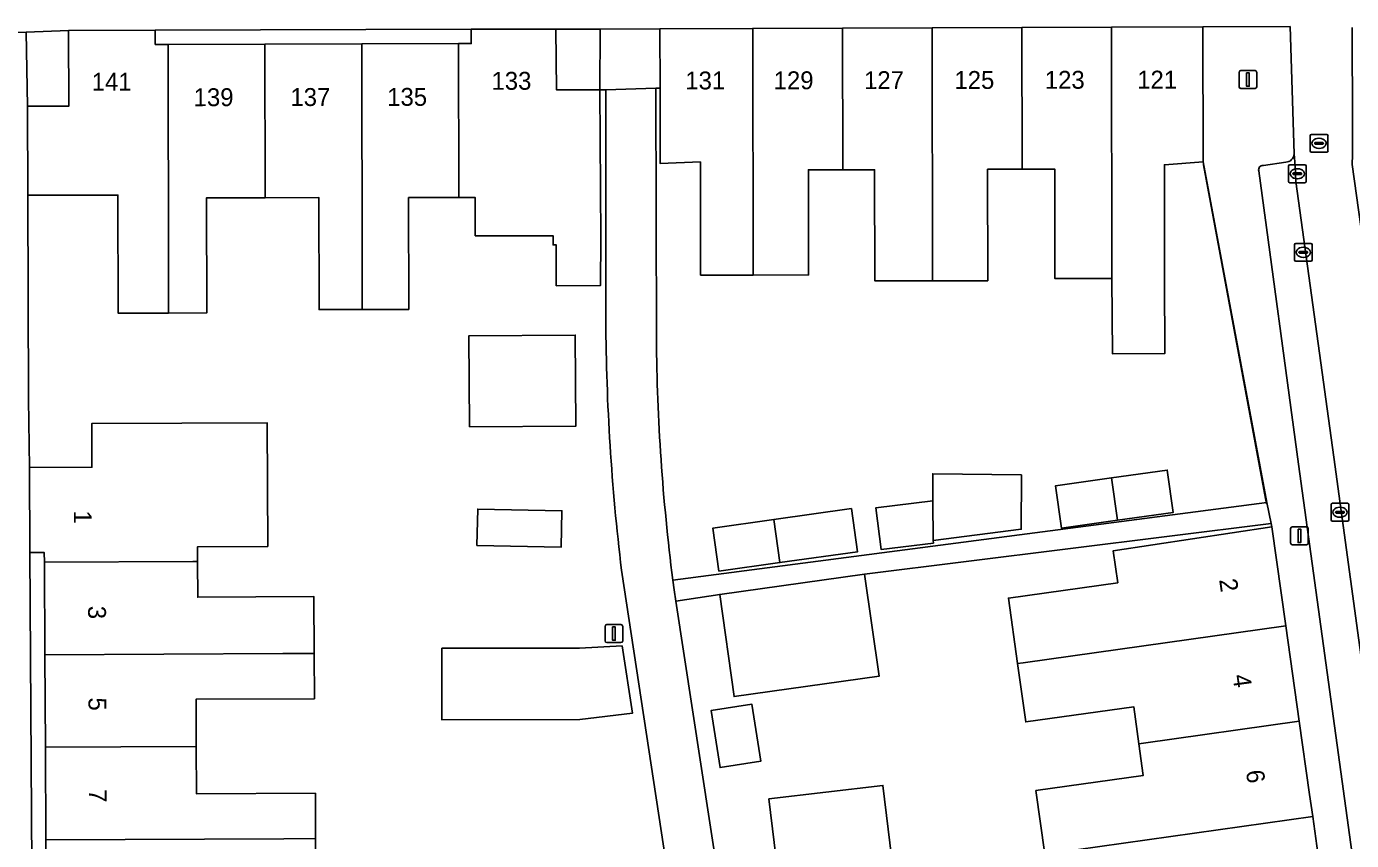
# Model space of a CAD drawing. Extents: x 159716 to 160783, y 383290 to 384031.
# Drawn here: x 160153 to 160227, y 383701.3 to 383746.8 of the extents above; entities that cross this region are included whole.
import ezdxf

# ---------------------------------------------------------------- set-up
doc = ezdxf.new("R2010")
doc.units = 0
for name, color, linetype in [('IMGEO_Erf', 7, 'Continuous'), ('IMGEO_Kolk', 7, 'Continuous'), ('IMGEO_Lichtmast', 7, 'Continuous'), ('IMGEO_Muur', 7, 'Continuous'), ('IMGEO_Pand', 7, 'Continuous'), ('IMGEO_Pand_nummerreeks', 7, 'Continuous'), ('IMGEO_Parkeervlak_open', 7, 'Continuous'), ('IMGEO_Rijbaan_lokaal_open', 7, 'Continuous'), ('IMGEO_Rioolput', 7, 'Continuous'), ('IMGEO_Voetpad_open', 7, 'Continuous')]:
    doc.layers.add(name, color=color, linetype=linetype)

msp = doc.modelspace()

# ---------------------------------------------------------------- linework, layer by layer
at = {"layer": 'IMGEO_Erf'}
for points in [[(160155.314, 383746.591), (160152.949, 383746.498), (160153.028, 383742.368), (160155.333, 383742.372)], [(160177.832, 383746.661), (160160.16, 383746.616), (160160.161, 383745.816), (160160.884, 383745.818), (160166.294, 383745.832), (160171.705, 383745.846), (160177.116, 383745.859), (160177.833, 383745.861)], [(160185.037, 383746.676), (160182.565, 383746.665), (160182.6, 383743.274), (160185.012, 383743.274)], [(160177.737, 383724.449), (160177.702, 383729.531), (160183.646, 383729.572), (160183.681, 383724.49)], [(160208.599, 383721.765), (160208.583, 383718.721), (160203.663, 383718.101), (160203.664, 383717.952), (160200.74, 383717.594), (160200.455, 383719.927), (160203.644, 383720.317), (160203.632, 383721.823)], [(160216.742, 383722.032), (160217.075, 383719.659), (160213.951, 383719.221), (160210.828, 383718.783), (160210.495, 383721.156), (160213.619, 383721.594)], [(160178.15, 383717.82), (160178.189, 383719.85), (160182.898, 383719.759), (160182.858, 383717.729)], [(160199.085, 383719.881), (160199.424, 383717.469), (160195.082, 383716.858), (160191.676, 383716.38), (160191.337, 383718.792), (160194.743, 383719.271)], [(160154.05, 383701.364), (160154.02, 383706.538), (160153.99, 383711.711), (160153.961, 383716.884), (160153.957, 383717.419), (160153.157, 383717.414), (160153.348, 383685.282), (160154.143, 383685.283), (160154.111, 383690.738), (160154.08, 383696.191)], [(160176.185, 383712.069), (160183.885, 383712.083), (160186.26, 383712.204), (160186.848, 383708.451), (160183.892, 383708.086), (160176.193, 383708.071)], [(160194.015, 383705.761), (160191.743, 383705.403), (160191.24, 383708.593), (160193.512, 383708.951)], [(160201.428, 383699.526), (160195.055, 383698.769), (160194.475, 383703.653), (160200.848, 383704.41)]]:
    msp.add_lwpolyline(points, close=True, dxfattribs=at)
for points in [[(160185.356, 383730.393), (160185.356, 383743.275), (160185.012, 383743.274), (160185.077, 383735), (160185.058, 383732.35), (160182.585, 383732.334), (160182.581, 383734.61), (160182.404, 383734.61), (160182.403, 383735.127), (160178.05, 383735.121), (160178.047, 383737.262), (160177.13, 383737.261), (160174.325, 383737.256), (160174.335, 383731.005), (160171.73, 383731.001), (160169.32, 383730.997), (160169.309, 383737.254), (160166.308, 383737.249), (160163.034, 383737.244), (160163.045, 383730.81), (160160.91, 383730.806), (160158.087, 383730.801), (160158.076, 383737.4), (160153.046, 383737.391), (160153.072, 383725.982), (160153.128, 383722.176), (160156.62, 383722.189), (160156.608, 383724.628), (160161.656, 383724.654), (160166.427, 383724.668), (160166.449, 383717.763), (160162.526, 383717.745), (160162.53, 383716.925), (160162.539, 383714.927), (160169.032, 383714.959), (160169.048, 383711.784), (160169.06, 383709.255), (160162.445, 383709.222), (160162.458, 383706.579), (160162.47, 383703.937), (160169.116, 383703.97), (160169.128, 383701.437), (160169.142, 383698.596)], [(160218.753, 383739.261), (160216.582, 383739.087), (160216.595, 383732.738), (160216.604, 383728.537), (160213.674, 383728.531), (160213.648, 383732.733), (160211.596, 383732.729), (160210.464, 383732.727), (160210.454, 383738.849), (160208.624, 383738.846), (160206.693, 383738.842), (160206.703, 383732.609), (160203.623, 383732.604), (160200.393, 383732.598), (160200.382, 383738.814), (160198.599, 383738.811), (160196.677, 383738.808), (160196.686, 383732.934), (160193.598, 383732.928), (160190.654, 383732.923), (160190.642, 383739.252), (160188.394, 383739.16), (160188.384, 383743.366), (160188.154, 383743.37), (160188.179, 383729.368)], [(160189.1, 383715.883), (160222.31, 383720.208), (160218.753, 383739.261)], [(160209.901, 383700.567), (160209.403, 383704.123), (160215.404, 383704.963), (160215.156, 383706.734), (160214.867, 383708.799), (160208.827, 383707.953), (160208.371, 383711.215), (160207.858, 383714.877), (160213.973, 383715.734), (160213.724, 383717.518), (160222.589, 383718.862), (160222.551, 383719.046), (160199.824, 383716.221), (160200.628, 383710.506), (160192.525, 383709.367), (160191.722, 383715.082), (160189.268, 383714.705), (160195.404, 383674.755)], [(160192.049, 383678.265), (160186.233, 383716.436)]]:
    msp.add_lwpolyline(points, dxfattribs=at)
for centre, radius, start, end in [((160305.947, 383730.964), 120.593, 180.27148, 186.91952), ((160302.297, 383730.388), 114.122, 180.51214, 187.30211)]:
    msp.add_arc(centre, radius, start, end, dxfattribs=at)
at = {"layer": 'IMGEO_Kolk'}
for p, q in [((160223.848, 383733.771), (160223.848, 383734.623)), ((160223.923, 383734.697), (160224.775, 383734.697)), ((160224.336, 383734.477), (160224.361, 383734.477)), ((160224.849, 383734.623), (160224.849, 383733.771)), ((160224.775, 383733.697), (160223.923, 383733.697)), ((160224.107, 383734.191), (160224.107, 383734.203)), ((160224.545, 383734.154), (160224.147, 383734.154)), ((160224.15, 383734.24), (160224.548, 383734.24)), ((160224.359, 383733.917), (160224.334, 383733.917)), ((160224.591, 383734.203), (160224.591, 383734.191)), ((160225.898, 383719.245), (160225.898, 383720.097)), ((160225.973, 383720.171), (160226.825, 383720.171)), ((160226.157, 383719.665), (160226.157, 383719.677)), ((160226.595, 383719.628), (160226.197, 383719.628)), ((160226.2, 383719.714), (160226.598, 383719.714)), ((160226.386, 383719.951), (160226.411, 383719.951)), ((160226.641, 383719.677), (160226.641, 383719.665)), ((160226.899, 383720.097), (160226.899, 383719.245)), ((160226.825, 383719.171), (160225.973, 383719.171)), ((160226.409, 383719.391), (160226.384, 383719.391))]:
    msp.add_line(p, q, dxfattribs=at)
for points in [[(160223.848, 383733.771), (160223.848, 383734.623)], [(160223.923, 383734.697), (160224.775, 383734.697)], [(160224.849, 383734.623), (160224.849, 383733.771)], [(160224.775, 383733.697), (160223.923, 383733.697)], [(160225.898, 383719.245), (160225.898, 383720.097)], [(160225.973, 383720.171), (160226.825, 383720.171)], [(160226.899, 383720.097), (160226.899, 383719.245)], [(160226.825, 383719.171), (160225.973, 383719.171)]]:
    msp.add_lwpolyline(points, dxfattribs=at)
for centre, radius, start, end in [((160223.925, 383734.621), 0.0765, 91.55205, 178.44795), ((160223.925, 383734.621), 0.0765, 91.55205, 178.44795), ((160224.773, 383734.621), 0.0765, 1.55205, 88.44795), ((160224.773, 383734.621), 0.0765, 1.55205, 88.44795), ((160223.925, 383733.773), 0.0765, 181.55205, 268.44795), ((160223.925, 383733.773), 0.0765, 181.55205, 268.44795), ((160224.147, 383734.2), 0.0403, 85.87752, 175.75265), ((160224.144, 383734.19), 0.0366, 178.93798, 274.71019), ((160224.548, 383734.197), 0.043, 264.86636, 352.45326), ((160224.552, 383734.202), 0.0386, 1.73085, 96.63898), ((160224.773, 383733.773), 0.0765, 271.55205, 358.44795), ((160224.773, 383733.773), 0.0765, 271.55205, 358.44795), ((160225.975, 383720.095), 0.0765, 91.55205, 178.44795), ((160225.975, 383720.095), 0.0765, 91.55205, 178.44795), ((160226.197, 383719.674), 0.0403, 85.87752, 175.75265), ((160226.194, 383719.664), 0.0366, 178.93798, 274.71019), ((160226.598, 383719.671), 0.043, 264.86636, 352.45326), ((160226.602, 383719.676), 0.0386, 1.73085, 96.63898), ((160226.823, 383720.095), 0.0765, 1.55205, 88.44795), ((160226.823, 383720.095), 0.0765, 1.55205, 88.44795), ((160225.975, 383719.247), 0.0765, 181.55205, 268.44795), ((160225.975, 383719.247), 0.0765, 181.55205, 268.44795), ((160226.823, 383719.247), 0.0765, 271.55205, 358.44795), ((160226.823, 383719.247), 0.0765, 271.55205, 358.44795)]:
    msp.add_arc(centre, radius, start, end, dxfattribs=at)
for centre, major_axis, ratio, start_param, end_param in [((160224.335, 383734.197), (-0.387, 0.002), 0.722429, 4.712389, 7.853982), ((160224.36, 383734.197), (-0.39, 0.002), 0.717154, 1.570796, 4.712389), ((160226.385, 383719.671), (-0.387, 0.002), 0.722429, 4.712389, 7.853982), ((160226.41, 383719.671), (-0.39, 0.002), 0.717154, 1.570796, 4.712389)]:
    msp.add_ellipse(centre, major_axis=major_axis, ratio=ratio, start_param=start_param, end_param=end_param, dxfattribs=at)
at = {"layer": 'IMGEO_Lichtmast'}
for p, q in [((160220.758, 383743.451), (160220.758, 383744.251)), ((160220.758, 383744.251), (160220.758, 383743.451)), ((160220.858, 383744.351), (160221.648, 383744.351)), ((160221.648, 383744.351), (160220.858, 383744.351)), ((160221.748, 383744.251), (160221.748, 383743.451)), ((160221.748, 383743.451), (160221.748, 383744.251)), ((160221.648, 383743.351), (160220.858, 383743.351)), ((160220.858, 383743.351), (160221.648, 383743.351)), ((160223.634, 383717.956), (160223.634, 383718.756)), ((160223.634, 383718.756), (160223.634, 383717.956)), ((160223.734, 383718.856), (160224.524, 383718.856)), ((160224.524, 383718.856), (160223.734, 383718.856)), ((160224.624, 383718.756), (160224.624, 383717.956)), ((160224.624, 383717.956), (160224.624, 383718.756)), ((160224.524, 383717.856), (160223.734, 383717.856)), ((160223.734, 383717.856), (160224.524, 383717.856)), ((160185.308, 383712.492), (160185.308, 383713.292)), ((160185.308, 383713.292), (160185.308, 383712.492)), ((160185.408, 383713.392), (160186.198, 383713.392)), ((160186.198, 383713.392), (160185.408, 383713.392)), ((160186.298, 383713.292), (160186.298, 383712.492)), ((160186.298, 383712.492), (160186.298, 383713.292)), ((160186.198, 383712.392), (160185.408, 383712.392)), ((160185.408, 383712.392), (160186.198, 383712.392))]:
    msp.add_line(p, q, dxfattribs=at)
for points in [[(160221.178, 383744.226), (160221.328, 383744.226), (160221.328, 383743.476), (160221.178, 383743.476), (160221.178, 383744.226)], [(160224.054, 383718.731), (160224.204, 383718.731), (160224.204, 383717.981), (160224.054, 383717.981), (160224.054, 383718.731)], [(160185.728, 383713.267), (160185.878, 383713.267), (160185.878, 383712.517), (160185.728, 383712.517), (160185.728, 383713.267)]]:
    msp.add_lwpolyline(points, dxfattribs=at)
for centre, start, end in [((160220.858, 383744.251), 90, 180), ((160220.858, 383744.251), 90, 180), ((160221.648, 383744.251), 0, 90), ((160221.648, 383744.251), 360, 90), ((160220.858, 383743.451), 180, 270), ((160220.858, 383743.451), 180, 270), ((160221.648, 383743.451), 270, 0), ((160221.648, 383743.451), 270, 0), ((160223.734, 383718.756), 90, 180), ((160223.734, 383718.756), 90, 180), ((160224.524, 383718.756), 0, 90), ((160224.524, 383718.756), 360, 90), ((160223.734, 383717.956), 180, 270), ((160223.734, 383717.956), 180, 270), ((160224.524, 383717.956), 270, 0), ((160224.524, 383717.956), 270, 0), ((160185.408, 383713.292), 90, 180), ((160185.408, 383713.292), 90, 180), ((160186.198, 383713.292), 0, 90), ((160186.198, 383713.292), 360, 90), ((160185.408, 383712.492), 180, 270), ((160185.408, 383712.492), 180, 270), ((160186.198, 383712.492), 270, 0), ((160186.198, 383712.492), 270, 0)]:
    msp.add_arc(centre, 0.1, start, end, dxfattribs=at)
at = {"layer": 'IMGEO_Muur'}
for points in [[(160218.771, 383739.091), (160222.296, 383720.136)], [(160153.046, 383737.391), (160153.072, 383725.982)]]:
    msp.add_lwpolyline(points, dxfattribs=at)
at = {"layer": 'IMGEO_Pand'}
for points in [[(160160.884, 383745.818), (160160.161, 383745.816), (160160.16, 383746.616), (160155.314, 383746.591), (160155.333, 383742.372), (160153.028, 383742.368), (160153.046, 383737.391), (160158.076, 383737.4), (160158.087, 383730.801), (160160.91, 383730.806), (160160.906, 383732.899)], [(160185.012, 383743.274), (160182.6, 383743.274), (160182.565, 383746.665), (160177.832, 383746.661), (160177.833, 383745.861), (160177.116, 383745.859), (160177.13, 383737.439), (160177.13, 383737.261), (160178.047, 383737.262), (160178.05, 383735.121), (160182.403, 383735.127), (160182.404, 383734.61), (160182.581, 383734.61), (160182.585, 383732.334), (160185.058, 383732.35), (160185.077, 383735)], [(160193.572, 383746.707), (160188.376, 383746.69), (160188.384, 383743.366), (160188.394, 383739.16), (160190.642, 383739.252), (160190.654, 383732.923), (160193.598, 383732.928)], [(160198.585, 383746.723), (160193.572, 383746.707), (160193.598, 383732.928), (160196.686, 383732.934), (160196.677, 383738.808), (160198.599, 383738.811)], [(160203.598, 383746.74), (160198.585, 383746.723), (160198.599, 383738.811), (160200.382, 383738.814), (160200.393, 383732.598), (160203.623, 383732.604), (160203.623, 383732.705)], [(160208.61, 383746.756), (160203.598, 383746.74), (160203.623, 383732.705), (160203.623, 383732.604), (160206.703, 383732.609), (160206.693, 383738.842), (160208.624, 383738.846), (160208.624, 383739.025)], [(160213.623, 383746.772), (160208.61, 383746.756), (160208.624, 383739.025), (160208.624, 383738.846), (160210.454, 383738.849), (160210.464, 383732.727), (160211.596, 383732.729), (160213.648, 383732.733)], [(160216.582, 383739.087), (160218.753, 383739.261), (160218.726, 383746.789), (160213.623, 383746.772), (160213.648, 383732.733), (160213.674, 383728.531), (160216.604, 383728.537), (160216.595, 383732.738)], [(160166.294, 383745.832), (160160.884, 383745.818), (160160.906, 383732.899), (160160.91, 383730.806), (160163.045, 383730.81), (160163.034, 383737.244), (160166.308, 383737.249), (160166.308, 383737.41)], [(160171.705, 383745.846), (160166.294, 383745.832), (160166.308, 383737.41), (160166.308, 383737.249), (160169.309, 383737.254), (160169.32, 383730.997), (160171.73, 383731.001), (160171.727, 383732.905)], [(160177.116, 383745.859), (160171.705, 383745.846), (160171.727, 383732.905), (160171.73, 383731.001), (160174.335, 383731.005), (160174.325, 383737.256), (160177.13, 383737.261), (160177.13, 383737.439)], [(160177.737, 383724.449), (160183.681, 383724.49), (160183.646, 383729.572), (160177.702, 383729.531)], [(160166.427, 383724.668), (160161.656, 383724.654), (160156.608, 383724.628), (160156.62, 383722.189), (160153.128, 383722.176), (160153.157, 383717.414), (160153.957, 383717.419), (160153.961, 383716.884), (160162.263, 383716.923), (160162.53, 383716.925), (160162.526, 383717.745), (160166.449, 383717.763)], [(160208.599, 383721.765), (160203.632, 383721.823), (160203.644, 383720.317), (160203.663, 383718.101), (160208.583, 383718.721)], [(160213.951, 383719.221), (160217.075, 383719.659), (160216.742, 383722.032), (160213.619, 383721.594)], [(160213.619, 383721.594), (160210.495, 383721.156), (160210.828, 383718.783), (160213.951, 383719.221)], [(160203.644, 383720.317), (160200.455, 383719.927), (160200.74, 383717.594), (160203.664, 383717.952), (160203.663, 383718.101)], [(160178.15, 383717.82), (160182.858, 383717.729), (160182.898, 383719.759), (160178.189, 383719.85)], [(160194.743, 383719.271), (160195.082, 383716.858), (160199.424, 383717.469), (160199.085, 383719.881)], [(160194.743, 383719.271), (160191.337, 383718.792), (160191.676, 383716.38), (160195.082, 383716.858)], [(160222.589, 383718.862), (160213.724, 383717.518), (160213.973, 383715.734), (160207.858, 383714.877), (160208.371, 383711.215), (160208.679, 383711.258), (160223.372, 383713.317)], [(160169.032, 383714.959), (160162.539, 383714.927), (160162.53, 383716.925), (160162.263, 383716.923), (160153.961, 383716.884), (160153.99, 383711.711), (160167.301, 383711.776), (160169.048, 383711.784)], [(160200.628, 383710.506), (160199.824, 383716.221), (160191.722, 383715.082), (160192.525, 383709.367)], [(160223.372, 383713.317), (160208.679, 383711.258), (160208.371, 383711.215), (160208.827, 383707.953), (160214.867, 383708.799), (160215.156, 383706.734), (160215.421, 383706.771), (160224.124, 383707.991)], [(160183.892, 383708.086), (160186.848, 383708.451), (160186.26, 383712.204), (160183.885, 383712.083), (160176.185, 383712.069), (160176.193, 383708.071)], [(160169.048, 383711.784), (160167.301, 383711.776), (160153.99, 383711.711), (160154.02, 383706.538), (160162.458, 383706.579), (160162.445, 383709.222), (160169.06, 383709.255)], [(160193.512, 383708.951), (160191.24, 383708.593), (160191.743, 383705.403), (160194.015, 383705.761)], [(160224.124, 383707.991), (160215.421, 383706.771), (160215.156, 383706.734), (160215.404, 383704.963), (160209.403, 383704.123), (160209.901, 383700.567), (160210.329, 383700.627), (160224.873, 383702.664), (160224.7, 383703.909)], [(160169.116, 383703.97), (160162.47, 383703.937), (160162.458, 383706.579), (160154.02, 383706.538), (160154.05, 383701.364), (160167.349, 383701.429), (160169.128, 383701.437)], [(160201.428, 383699.526), (160200.848, 383704.41), (160194.475, 383703.653), (160195.055, 383698.769)], [(160224.873, 383702.664), (160210.329, 383700.627), (160209.901, 383700.567), (160205.61, 383699.966), (160206.053, 383696.806), (160210.344, 383697.407), (160216.339, 383698.247), (160216.642, 383696.079), (160216.889, 383696.114), (160225.615, 383697.337)], [(160162.575, 383698.564), (160166.117, 383698.581), (160169.142, 383698.596), (160169.128, 383701.437), (160167.349, 383701.429), (160154.05, 383701.364), (160154.08, 383696.191), (160162.312, 383696.232), (160162.586, 383696.233)]]:
    msp.add_lwpolyline(points, close=True, dxfattribs=at)
at = {"layer": 'IMGEO_Parkeervlak_open'}
for points in [[(160228.912, 383701.88), (160226.055, 383722.742), (160223.935, 383738.148), (160223.898, 383739.006), (160223.833, 383739.706)], [(160221.858, 383738.755), (160224.075, 383722.353), (160230.414, 383676.339), (160230.994, 383672.299)], [(160223.364, 383739.235), (160222.114, 383739.053)]]:
    msp.add_lwpolyline(points, dxfattribs=at)
for centre, radius, start, end in [((160223.355, 383739.713), 0.478, 271.09867, 359.14514), ((160222.089, 383738.815), 0.239, 84.06933, 194.60153)]:
    msp.add_arc(centre, radius, start, end, dxfattribs=at)
at = {"layer": 'IMGEO_Rijbaan_lokaal_open'}
for points in [[(160148.407, 383684.961), (160153.348, 383685.282), (160153.157, 383717.414), (160153.128, 383722.176), (160153.072, 383725.982), (160153.046, 383737.391), (160153.028, 383742.368), (160152.949, 383746.498)], [(160223.833, 383739.706), (160223.612, 383746.816), (160218.726, 383746.789), (160218.753, 383739.261), (160222.31, 383720.208), (160222.551, 383719.046), (160222.589, 383718.862), (160223.372, 383713.317), (160224.124, 383707.991), (160224.7, 383703.909), (160224.873, 383702.664), (160225.615, 383697.337)], [(160223.612, 383746.816), (160223.833, 383739.706), (160223.898, 383739.006), (160223.935, 383738.148), (160226.055, 383722.742), (160228.912, 383701.88), (160232.18, 383702.315), (160231.558, 383706.805), (160231.311, 383708.492), (160231.158, 383709.718), (160230.618, 383713.556), (160228.88, 383726.194), (160228.773, 383726.987), (160227.082, 383739.102), (160227.092, 383739.638), (160227.094, 383741.298), (160227.08, 383746.76)], [(160224.075, 383722.353), (160221.858, 383738.755)], [(160222.114, 383739.053), (160223.364, 383739.235)], [(160230.994, 383672.299), (160230.414, 383676.339), (160224.075, 383722.353)]]:
    msp.add_lwpolyline(points, dxfattribs=at)
for centre, radius, start, end in [((160157.337, 383744.599), 8.157, 104.90497, 167.10486), ((160223.355, 383739.713), 0.478, 271.09867, 359.14514), ((160222.089, 383738.815), 0.239, 84.06933, 194.60153)]:
    msp.add_arc(centre, radius, start, end, dxfattribs=at)
at = {"layer": 'IMGEO_Rioolput'}
for p, q in [((160224.728, 383739.862), (160224.728, 383740.714)), ((160224.803, 383740.788), (160225.655, 383740.788)), ((160224.987, 383740.282), (160224.987, 383740.294)), ((160225.425, 383740.245), (160225.027, 383740.245)), ((160225.03, 383740.331), (160225.428, 383740.331)), ((160225.216, 383740.568), (160225.241, 383740.568)), ((160225.471, 383740.294), (160225.471, 383740.282)), ((160225.729, 383740.714), (160225.729, 383739.862)), ((160225.655, 383739.788), (160224.803, 383739.788)), ((160225.239, 383740.008), (160225.214, 383740.008)), ((160223.512, 383738.163), (160223.512, 383739.015)), ((160223.587, 383739.089), (160224.439, 383739.089)), ((160224, 383738.869), (160224.025, 383738.869)), ((160224.513, 383739.015), (160224.513, 383738.163)), ((160224.439, 383738.089), (160223.587, 383738.089)), ((160223.771, 383738.583), (160223.771, 383738.595)), ((160224.209, 383738.546), (160223.811, 383738.546)), ((160223.814, 383738.632), (160224.212, 383738.632)), ((160224.023, 383738.309), (160223.998, 383738.309)), ((160224.255, 383738.595), (160224.255, 383738.583))]:
    msp.add_line(p, q, dxfattribs=at)
for points in [[(160224.728, 383739.862), (160224.728, 383740.714)], [(160224.803, 383740.788), (160225.655, 383740.788)], [(160225.729, 383740.714), (160225.729, 383739.862)], [(160225.655, 383739.788), (160224.803, 383739.788)], [(160223.512, 383738.163), (160223.512, 383739.015)], [(160223.587, 383739.089), (160224.439, 383739.089)], [(160224.513, 383739.015), (160224.513, 383738.163)], [(160224.439, 383738.089), (160223.587, 383738.089)]]:
    msp.add_lwpolyline(points, dxfattribs=at)
for centre, radius, start, end in [((160224.805, 383740.712), 0.0765, 91.55205, 178.44795), ((160224.805, 383740.712), 0.0765, 91.55205, 178.44795), ((160225.027, 383740.291), 0.0403, 85.87752, 175.75265), ((160225.024, 383740.281), 0.0366, 178.93798, 274.71019), ((160225.428, 383740.288), 0.043, 264.86636, 352.45326), ((160225.432, 383740.293), 0.0386, 1.73085, 96.63898), ((160225.653, 383740.712), 0.0765, 1.55205, 88.44795), ((160225.653, 383740.712), 0.0765, 1.55205, 88.44795), ((160224.805, 383739.864), 0.0765, 181.55205, 268.44795), ((160224.805, 383739.864), 0.0765, 181.55205, 268.44795), ((160225.653, 383739.864), 0.0765, 271.55205, 358.44795), ((160225.653, 383739.864), 0.0765, 271.55205, 358.44795), ((160223.589, 383739.013), 0.0765, 91.55205, 178.44795), ((160223.589, 383739.013), 0.0765, 91.55205, 178.44795), ((160224.437, 383739.013), 0.0765, 1.55205, 88.44795), ((160224.437, 383739.013), 0.0765, 1.55205, 88.44795), ((160223.589, 383738.165), 0.0765, 181.55205, 268.44795), ((160223.589, 383738.165), 0.0765, 181.55205, 268.44795), ((160223.811, 383738.592), 0.0403, 85.87752, 175.75265), ((160223.808, 383738.582), 0.0366, 178.93798, 274.71019), ((160224.212, 383738.589), 0.043, 264.86636, 352.45326), ((160224.216, 383738.594), 0.0386, 1.73085, 96.63898), ((160224.437, 383738.165), 0.0765, 271.55205, 358.44795), ((160224.437, 383738.165), 0.0765, 271.55205, 358.44795)]:
    msp.add_arc(centre, radius, start, end, dxfattribs=at)
for centre, major_axis, ratio, start_param, end_param in [((160225.215, 383740.288), (-0.387, 0.002), 0.722429, 4.712389, 7.853982), ((160225.24, 383740.288), (-0.39, 0.002), 0.717154, 1.570796, 4.712389), ((160223.999, 383738.589), (-0.387, 0.002), 0.722429, 4.712389, 7.853982), ((160224.024, 383738.589), (-0.39, 0.002), 0.717154, 1.570796, 4.712389)]:
    msp.add_ellipse(centre, major_axis=major_axis, ratio=ratio, start_param=start_param, end_param=end_param, dxfattribs=at)
at = {"layer": 'IMGEO_Voetpad_open'}
for points in [[(160149.386, 383746.419), (160152.949, 383746.498), (160155.314, 383746.591), (160160.16, 383746.616), (160177.832, 383746.661), (160182.565, 383746.665), (160185.037, 383746.676), (160188.376, 383746.69), (160193.572, 383746.707), (160198.585, 383746.723), (160203.598, 383746.74), (160208.61, 383746.756), (160213.623, 383746.772), (160218.726, 383746.789), (160223.612, 383746.816)], [(160188.179, 383729.368), (160188.154, 383743.37), (160185.356, 383743.275), (160185.356, 383730.393)], [(160186.233, 383716.436), (160192.049, 383678.265), (160192.874, 383672.849), (160196.406, 383647.105), (160196.781, 383644.368), (160199.575, 383644.793), (160195.404, 383674.755), (160189.268, 383714.705)], [(160189.268, 383714.705), (160189.172, 383715.331), (160189.1, 383715.883)]]:
    msp.add_lwpolyline(points, dxfattribs=at)
for points in [[(160188.376, 383746.69), (160185.037, 383746.676), (160185.012, 383743.274), (160185.356, 383743.275), (160188.154, 383743.37), (160188.384, 383743.366)], [(160222.551, 383719.046), (160222.31, 383720.208), (160189.1, 383715.883), (160189.172, 383715.331), (160189.268, 383714.705), (160191.722, 383715.082), (160199.824, 383716.221)]]:
    msp.add_lwpolyline(points, close=True, dxfattribs=at)
for centre, radius, start, end in [((160157.337, 383744.599), 8.157, 104.90497, 167.10486), ((160305.947, 383730.964), 120.593, 180.27148, 186.91952), ((160302.297, 383730.388), 114.122, 180.51214, 187.30211)]:
    msp.add_arc(centre, radius, start, end, dxfattribs=at)

# ---------------------------------------------------------------- texts
at = {"layer": 'IMGEO_Pand_nummerreeks'}
for s, rotation, p in [('141', 0.09167, (160156.608, 383743.227)), ('133', 0.0974, (160178.962, 383743.279)), ('131', 0.0974, (160189.798, 383743.299)), ('129', 0.0974, (160194.737, 383743.308)), ('127', 0.0974, (160199.79, 383743.317)), ('125', 0.0974, (160204.843, 383743.326)), ('123', 0.0974, (160209.896, 383743.335)), ('121', 0.0974, (160215.063, 383743.344)), ('139', 0.0974, (160162.308, 383742.364)), ('137', 0.0974, (160167.719, 383742.373)), ('135', 0.0974, (160173.13, 383742.382)), ('1', 270.24043, (160155.61, 383719.771)), ('2', 277.96963, (160219.64, 383715.902)), ('3', 270.2347, (160156.406, 383714.444)), ('4', 277.96963, (160220.389, 383710.555)), ('5', 270.2347, (160156.427, 383709.321)), ('6', 277.96963, (160221.138, 383705.21)), ('7', 270.2347, (160156.448, 383704.198))]:
    msp.add_text(s, height=1, rotation=rotation, dxfattribs=at).set_placement(p)

doc.saveas('drawing.dxf')
